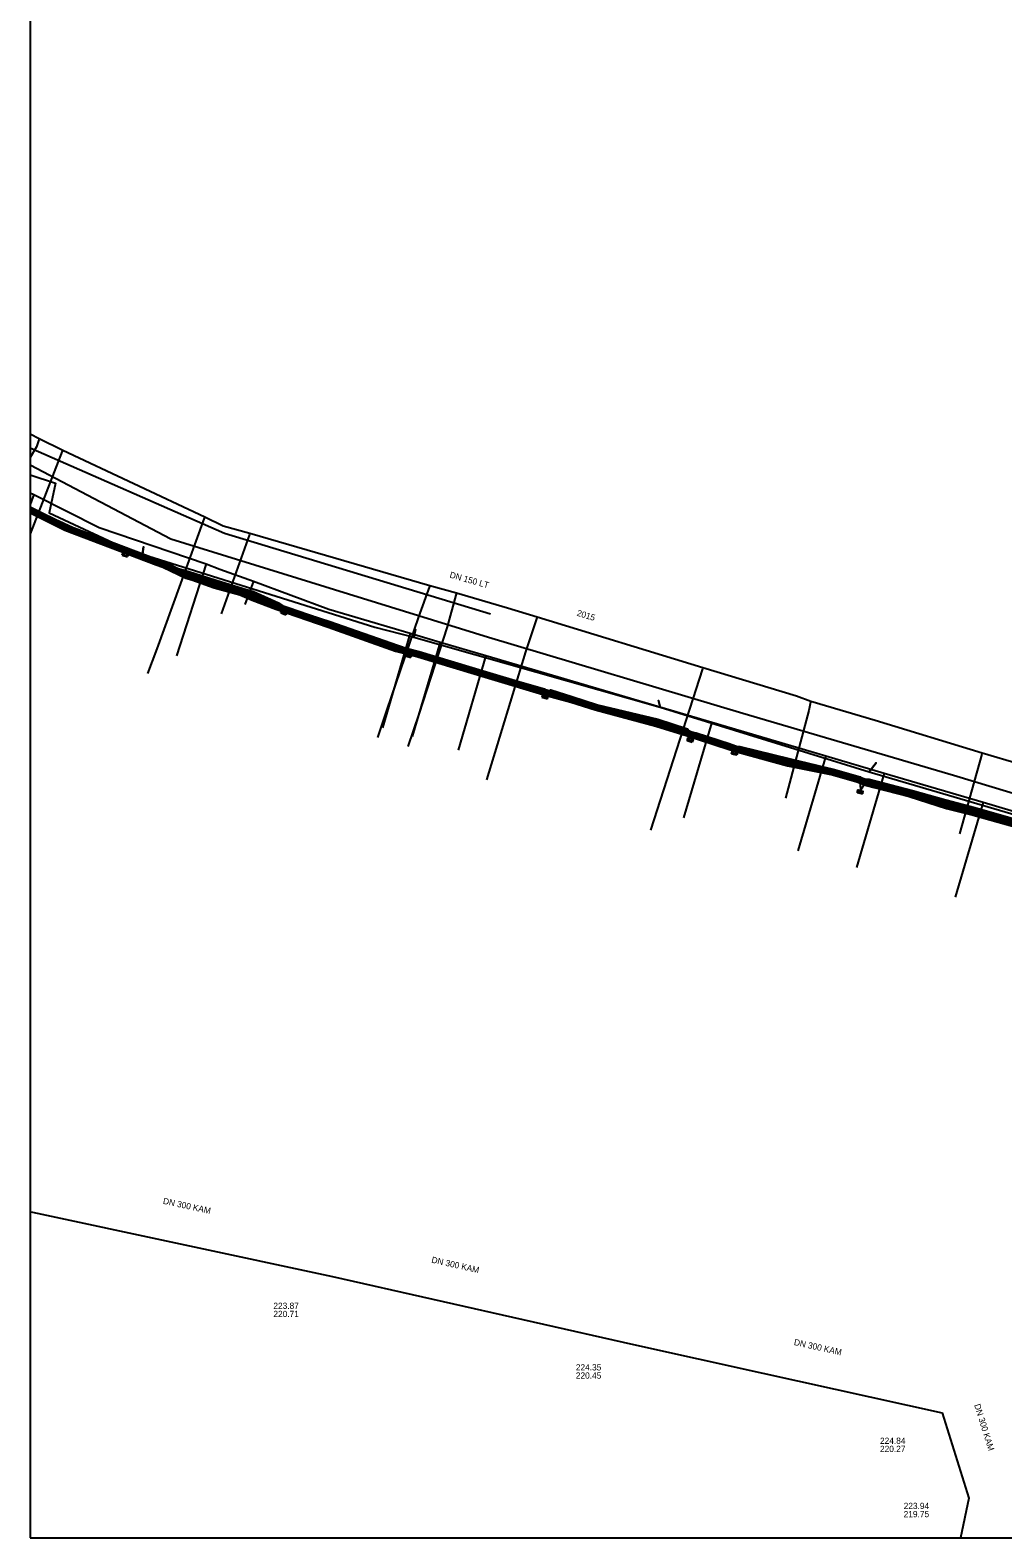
# Model space of a CAD drawing. Extents: x -599951 to -598963, y -1164095 to -1162939.
# Drawn here: x -599951.1 to -599826.1, y -1164094.7 to -1163901.1 of the extents above; entities that cross this region are included whole.
import ezdxf

# ---------------------------------------------------------------- set-up
doc = ezdxf.new("R2010")
doc.units = 0
for name, color, linetype in [('28', 7, 'Continuous'), ('31', 7, 'Continuous'), ('Level 1', 7, 'Continuous'), ('Vrstva 1', 7, 'Continuous'), ('Vrstva 13', 7, 'Continuous'), ('Vrstva 15', 7, 'Continuous'), ('Vrstva 16', 7, 'Continuous'), ('Vrstva 19', 7, 'Continuous'), ('Vrstva 42', 7, 'Continuous'), ('Vrstva 43', 7, 'Continuous'), ('Vrstva 44', 7, 'Continuous'), ('Vrstva 5', 7, 'Continuous'), ('Vrstva 53', 7, 'Continuous'), ('Vrstva 55', 7, 'Continuous'), ('Vrstva 58', 7, 'Continuous'), ('Vrstva 8', 7, 'Continuous')]:
    doc.layers.add(name, color=color, linetype=linetype)

# ---------------------------------------------------------------- blocks, each defined once
blk = doc.blocks.new('NN630')
at = {"layer": '31'}
for points in [[(-0.003, -0.7), (-0.703, 0)], [(-0.703, -0.7), (-0.703, 0), (0.697, 0), (0.697, -0.7)], [(-0.003, -0.7), (0.697, 0)], [(-0.703, -0.7), (0.697, -0.7)]]:
    blk.add_lwpolyline(points, dxfattribs=at)
blk = doc.blocks.new('NN620')
at = {"layer": '28'}
for points in [[(0.752, 0.004), (-0.748, 0.004)], [(-0.748, 0.004), (-0.748, -0.746)], [(0.752, -0.746), (0.752, 0.004)], [(-0.748, -0.746), (0.752, -0.746)], [(0.368, -0.18), (-0.376, -0.18)], [(-0.376, -0.18), (-0.376, -0.558)], [(-0.376, -0.558), (0.368, -0.558)], [(0.321, -0.227), (-0.329, -0.227)], [(-0.329, -0.227), (-0.329, -0.51)], [(-0.329, -0.51), (0.321, -0.51)], [(0.274, -0.274), (-0.281, -0.274)], [(-0.281, -0.274), (-0.281, -0.463)], [(-0.281, -0.463), (0.274, -0.463)], [(0.227, -0.321), (-0.234, -0.321)], [(-0.234, -0.321), (-0.234, -0.416)], [(-0.234, -0.416), (0.227, -0.416)], [(-0.193, -0.369), (0.185, -0.369)], [(0.227, -0.416), (0.227, -0.321)], [(0.274, -0.463), (0.274, -0.274)], [(0.321, -0.51), (0.321, -0.227)], [(0.368, -0.558), (0.368, -0.18)]]:
    blk.add_lwpolyline(points, dxfattribs=at)

msp = doc.modelspace()

# ---------------------------------------------------------------- linework, layer by layer
at = {"layer": 'Level 1'}
msp.add_line((-599926.14, -1163965.72), (-599951.125, -1163954.755), dxfattribs=at)
msp.add_lwpolyline([(-599891.96, -1163976.04), (-599926.14, -1163965.72)], dxfattribs=at)
at = {"layer": 'Vrstva 1'}
for p, q in [((-599926.14, -1163965.72), (-599951.125, -1163954.755)), ((-599891.96, -1163976.04), (-599926.14, -1163965.72))]:
    msp.add_line(p, q, dxfattribs=at)
at = {"layer": 'Vrstva 13'}
for points in [[(-599951.125, -1163952.918), (-599949.96, -1163953.52), (-599946.91, -1163954.98), (-599928.693, -1163963.548), (-599926.32, -1163964.71), (-599922.88, -1163965.66), (-599899.76, -1163972.37), (-599896.35, -1163973.33), (-599889.787, -1163975.267), (-599885.98, -1163976.39), (-599864.68, -1163982.92), (-599852.64, -1163986.57), (-599850.8, -1163987.22), (-599842.53, -1163989.68), (-599828.77, -1163993.88), (-599818.92, -1163996.8)], [(-599949.96, -1163953.52), (-599950.028, -1163953.686), (-599950.32, -1163954.59), (-599951.125, -1163955.956)], [(-599946.91, -1163954.98), (-599946.99, -1163955.13), (-599951.125, -1163965.737)], [(-599928.693, -1163963.548), (-599928.77, -1163963.73), (-599934.837, -1163980.507), (-599936.057, -1163983.688)], [(-599922.88, -1163965.66), (-599922.938, -1163965.82), (-599926.594, -1163976.031)], [(-599899.76, -1163972.37), (-599899.818, -1163972.529), (-599901.22, -1163976.42), (-599905.32, -1163988.42), (-599906.479, -1163991.902)], [(-599896.35, -1163973.33), (-599896.43, -1163973.61), (-599897.54, -1163977.7), (-599901.19, -1163988.92), (-599902.608, -1163993.068)], [(-599885.98, -1163976.39), (-599886.03, -1163976.536), (-599887.48, -1163980.89), (-599892.48, -1163997.355)], [(-599864.68, -1163982.92), (-599864.734, -1163983.09), (-599871.419, -1164003.786)], [(-599850.8, -1163987.22), (-599850.835, -1163987.348), (-599851.07, -1163988.42), (-599854.064, -1163999.693)], [(-599828.77, -1163993.88), (-599828.818, -1163994.062), (-599831.709, -1164004.271)]]:
    msp.add_lwpolyline(points, dxfattribs=at)
at = {"layer": 'Vrstva 16'}
msp.add_line((-599950.66, -1163960.7), (-599951.125, -1163961.971), dxfattribs=at)
for points in [[(-599951.125, -1163960.491), (-599950.66, -1163960.7), (-599942.27, -1163964.92), (-599928.49, -1163969.58), (-599926.77, -1163970.3), (-599922.43, -1163971.82), (-599912.76, -1163975.43), (-599902.28, -1163978.51), (-599898.44, -1163979.65), (-599892.56, -1163981.38), (-599863.53, -1163989.93), (-599848.86, -1163994.26), (-599841.36, -1163996.47), (-599828.66, -1164000.21), (-599821.46, -1164002.33)], [(-599928.49, -1163969.58), (-599932.31, -1163981.4)], [(-599922.43, -1163971.82), (-599923.52, -1163974.82)], [(-599902.28, -1163978.51), (-599905.86, -1163990.67)], [(-599898.44, -1163979.65), (-599902.02, -1163991.79)], [(-599892.56, -1163981.38), (-599896.14, -1163993.51)], [(-599863.53, -1163989.93), (-599867.15, -1164002.21)], [(-599848.86, -1163994.26), (-599852.46, -1164006.47)], [(-599841.36, -1163996.47), (-599844.94, -1164008.58)], [(-599828.66, -1164000.21), (-599832.25, -1164012.41)]]:
    msp.add_lwpolyline(points, dxfattribs=at)
at = {"layer": 'Vrstva 19'}
msp.add_lwpolyline([(-599951.125, -1163956.879), (-599933.03, -1163966.38), (-599892.24, -1163979.02), (-599859.53, -1163988.78), (-599832.49, -1163996.75), (-599788.49, -1164009.99), (-599755.73, -1164019.59), (-599723.17, -1164029.22), (-599687.59, -1164039.86)], dxfattribs=at)
at = {"layer": 'Vrstva 42'}
for points in [[(-599951.125, -1163962.512), (-599950.901, -1163962.608), (-599947.449, -1163964.059), (-599939.348, -1163967.839), (-599938.556, -1163968.123), (-599937.145, -1163968.466), (-599936.23, -1163968.928), (-599935.077, -1163969.363), (-599934.575, -1163969.483), (-599930.732, -1163970.584), (-599927.2, -1163971.675), (-599923.771, -1163972.754), (-599922.415, -1163973.146), (-599919.222, -1163974.622), (-599918.557, -1163975.035), (-599918.447, -1163975.186), (-599918.205, -1163975.283), (-599917.909, -1163975.295), (-599912.608, -1163976.995), (-599903.937, -1163980.035), (-599902.558, -1163980.505), (-599902.369, -1163980.655), (-599902.155, -1163980.707), (-599901.911, -1163980.664), (-599892.112, -1163983.624), (-599885.028, -1163985.649), (-599884.813, -1163986.454)], [(-599951.125, -1163962.729), (-599950.979, -1163962.792), (-599947.531, -1163964.241), (-599939.432, -1163968.021), (-599938.84, -1163968.24), (-599938.604, -1163968.317), (-599937.215, -1163968.654), (-599936.31, -1163969.112), (-599935.135, -1163969.554), (-599934.625, -1163969.677), (-599930.789, -1163970.776), (-599927.26, -1163971.865), (-599923.829, -1163972.946), (-599922.485, -1163973.334), (-599919.318, -1163974.798), (-599918.578, -1163975.261), (-599918.48, -1163975.69), (-599918.045, -1163975.449), (-599917.674, -1163975.58), (-599912.672, -1163977.185), (-599904.003, -1163980.225), (-599902.562, -1163980.716), (-599902.45, -1163981.19), (-599902.033, -1163980.838), (-599892.168, -1163983.816), (-599885.192, -1163985.811), (-599885.007, -1163986.506)], [(-599884.972, -1163986.402), (-599884.211, -1163985.799), (-599881.51, -1163986.625), (-599878.213, -1163987.714), (-599870.453, -1163989.544), (-599866.649, -1163990.805), (-599866.5, -1163990.984), (-599865.838, -1163991.294), (-599865.559, -1163991.315), (-599861.169, -1163992.735), (-599860.887, -1163992.907), (-599860.254, -1163993.063), (-599859.916, -1163993.043), (-599853.476, -1163994.623), (-599847.774, -1163996.013), (-599844.482, -1163996.964), (-599844.238, -1163997.122), (-599843.666, -1163997.253), (-599843.305, -1163997.233), (-599837.754, -1163998.693), (-599833.454, -1163999.904), (-599829.724, -1164000.884), (-599822.402, -1164002.984)], [(-599884.848, -1163986.558), (-599884.169, -1163986.021), (-599881.57, -1163986.815), (-599878.267, -1163987.906), (-599870.507, -1163989.736), (-599866.637, -1163991.019), (-599866.27, -1163992.05), (-599865.85, -1163991.68), (-599865.668, -1163991.491), (-599861.029, -1163992.991), (-599860.7, -1163993.3), (-599860.55, -1163993.74), (-599860.023, -1163993.221), (-599859.72, -1163993.297), (-599853.524, -1163994.817), (-599847.826, -1163996.207), (-599844.505, -1163997.167), (-599844.44, -1163998.72), (-599843.86, -1163997.82), (-599843.594, -1163997.574), (-599843.416, -1163997.41), (-599837.806, -1163998.886), (-599833.506, -1164000.096), (-599829.777, -1164001.076), (-599822.424, -1164003.186)]]:
    msp.add_lwpolyline(points, dxfattribs=at)
at = {"layer": 'Vrstva 44'}
for points in [[(-599951.125, -1163962.276), (-599946.38, -1163964.645), (-599934.695, -1163969.059), (-599933.793, -1163969.393), (-599930.872, -1163970.779), (-599930.127, -1163971.005), (-599927.251, -1163972.003), (-599923.95, -1163972.916), (-599922.348, -1163973.612), (-599919.319, -1163974.748), (-599912.601, -1163977.057), (-599903.972, -1163980.123), (-599901.119, -1163980.861), (-599892.044, -1163983.603), (-599884.617, -1163985.822)], [(-599951.125, -1163962.499), (-599946.46, -1163964.828), (-599934.765, -1163969.246), (-599933.871, -1163969.578), (-599930.951, -1163970.964), (-599930.189, -1163971.195), (-599927.31, -1163972.194), (-599924.017, -1163973.105), (-599922.423, -1163973.797), (-599919.386, -1163974.936), (-599912.667, -1163977.246), (-599904.031, -1163980.314), (-599901.173, -1163981.054), (-599892.101, -1163983.794), (-599884.672, -1163986.014)], [(-599930.98, -1163971.06), (-599933.91, -1163969.67), (-599934.8, -1163969.34), (-599946.5, -1163964.92), (-599951.125, -1163962.611)], [(-599951.125, -1163962.723), (-599946.54, -1163965.012), (-599934.835, -1163969.434), (-599933.949, -1163969.762), (-599931.023, -1163971.151), (-599930.251, -1163971.385), (-599927.37, -1163972.386), (-599924.083, -1163973.294), (-599922.497, -1163973.983), (-599919.454, -1163975.124), (-599912.733, -1163977.434), (-599904.089, -1163980.506), (-599901.227, -1163981.246), (-599892.159, -1163983.986), (-599884.728, -1163986.206)], [(-599951.125, -1163962.946), (-599946.62, -1163965.195), (-599934.905, -1163969.621), (-599934.027, -1163969.947), (-599931.088, -1163971.341), (-599930.313, -1163971.575), (-599927.429, -1163972.577), (-599924.15, -1163973.484), (-599922.572, -1163974.168), (-599919.521, -1163975.312), (-599912.799, -1163977.623), (-599904.148, -1163980.697), (-599901.281, -1163981.439), (-599892.216, -1163984.177), (-599884.783, -1163986.398)], [(-599930.98, -1163971.06), (-599930.22, -1163971.29), (-599927.34, -1163972.29), (-599924.05, -1163973.2), (-599922.46, -1163973.89), (-599919.42, -1163975.03), (-599912.7, -1163977.34), (-599904.06, -1163980.41), (-599901.2, -1163981.15), (-599892.13, -1163983.89), (-599884.7, -1163986.11), (-599881.55, -1163986.98), (-599878.42, -1163987.98), (-599870.62, -1163990.06), (-599866.56, -1163991.32), (-599861.32, -1163993), (-599860.07, -1163993.42), (-599853.73, -1163995.13), (-599847.94, -1163996.29), (-599844.77, -1163997.21), (-599843.52, -1163997.68), (-599842.56, -1163997.92), (-599838.04, -1163999.11), (-599833.27, -1164000.62), (-599829.82, -1164001.49), (-599822.36, -1164003.58)], [(-599884.783, -1163986.398), (-599881.636, -1163987.268), (-599878.504, -1163988.268), (-599870.703, -1163990.348), (-599866.65, -1163991.606), (-599861.414, -1163993.285), (-599860.157, -1163993.707), (-599853.799, -1163995.422), (-599848.011, -1163996.582), (-599844.865, -1163997.495), (-599843.609, -1163997.967), (-599842.635, -1163998.211), (-599838.123, -1163999.398), (-599833.352, -1164000.909), (-599829.897, -1164001.78), (-599822.434, -1164003.871)], [(-599884.728, -1163986.206), (-599881.579, -1163987.076), (-599878.448, -1163988.076), (-599870.648, -1163990.156), (-599866.59, -1163991.415), (-599861.351, -1163993.095), (-599860.099, -1163993.516), (-599853.753, -1163995.227), (-599847.964, -1163996.387), (-599844.802, -1163997.305), (-599843.55, -1163997.776), (-599842.585, -1163998.017), (-599838.068, -1163999.206), (-599833.297, -1164000.716), (-599829.846, -1164001.587), (-599822.385, -1164003.677)], [(-599884.672, -1163986.014), (-599881.521, -1163986.884), (-599878.392, -1163987.884), (-599870.592, -1163989.964), (-599866.53, -1163991.225), (-599861.289, -1163992.905), (-599860.041, -1163993.324), (-599853.707, -1163995.033), (-599847.916, -1163996.193), (-599844.738, -1163997.115), (-599843.49, -1163997.584), (-599842.535, -1163997.823), (-599838.012, -1163999.014), (-599833.243, -1164000.524), (-599829.794, -1164001.393), (-599822.335, -1164003.483)], [(-599884.617, -1163985.822), (-599881.464, -1163986.692), (-599878.336, -1163987.692), (-599870.537, -1163989.772), (-599866.47, -1163991.034), (-599861.226, -1163992.715), (-599859.983, -1163993.133), (-599853.661, -1163994.838), (-599847.869, -1163995.998), (-599844.675, -1163996.925), (-599843.431, -1163997.393), (-599842.485, -1163997.629), (-599837.957, -1163998.822), (-599833.188, -1164000.331), (-599829.743, -1164001.2), (-599822.286, -1164003.289)]]:
    msp.add_lwpolyline(points, dxfattribs=at)
at = {"layer": 'Vrstva 5'}
for p, q in [((-599951.125, -1164052.826), (-599950.82, -1164052.85)), ((-599950.82, -1164052.85), (-599912.29, -1164061.14)), ((-599912.29, -1164061.14), (-599873.59, -1164069.86)), ((-599833.92, -1164078.65), (-599830.51, -1164089.59)), ((-599830.51, -1164089.59), (-599831.58, -1164094.695))]:
    msp.add_line(p, q, dxfattribs=at)
msp.add_lwpolyline([(-599873.59, -1164069.86), (-599856.958, -1164073.545), (-599833.92, -1164078.65)], dxfattribs=at)
at = {"layer": 'Vrstva 53'}
msp.add_lwpolyline([(-599951.125, -1164094.695), (-598963.215, -1164094.695), (-598963.215, -1162939.4), (-599951.125, -1162939.4)], close=True, dxfattribs=at)
at = {"layer": 'Vrstva 55'}
msp.add_lwpolyline([(-599951.125, -1163958.165), (-599947.86, -1163959.25), (-599948.7, -1163963.03), (-599937.861, -1163968.08), (-599936.673, -1163968.349), (-599936.558, -1163967.429), (-599936.673, -1163968.349), (-599906.813, -1163977.74), (-599901.83, -1163979.005), (-599901.6, -1163978.046), (-599901.83, -1163979.005), (-599870.169, -1163988.012), (-599870.361, -1163987.131), (-599870.169, -1163988.012), (-599843.3, -1163996.292), (-599842.418, -1163995.142), (-599843.3, -1163996.292), (-599814.169, -1164004.878)], dxfattribs=at)
at = {"layer": 'Vrstva 58'}
for points in [[(-599822.31, -1164003.386), (-599829.769, -1164001.297), (-599833.215, -1164000.428), (-599837.984, -1163998.918), (-599842.51, -1163997.726), (-599843.46, -1163997.489), (-599844.707, -1163997.02), (-599847.892, -1163996.096), (-599853.684, -1163994.935), (-599860.012, -1163993.229), (-599861.258, -1163992.81), (-599866.5, -1163991.129), (-599870.565, -1163989.868), (-599878.364, -1163987.788), (-599881.493, -1163986.788), (-599884.645, -1163985.918), (-599892.072, -1163983.699), (-599901.146, -1163980.957), (-599904.001, -1163980.219), (-599912.634, -1163977.151), (-599919.352, -1163974.842), (-599922.385, -1163973.704), (-599923.983, -1163973.011), (-599927.28, -1163972.099), (-599930.158, -1163971.1), (-599930.908, -1163970.873), (-599933.832, -1163969.486), (-599934.73, -1163969.153), (-599946.42, -1163964.737), (-599951.125, -1163962.387)], [(-599951.125, -1163962.611), (-599946.5, -1163964.92), (-599934.8, -1163969.34), (-599933.91, -1163969.67), (-599930.98, -1163971.06), (-599930.22, -1163971.29), (-599927.34, -1163972.29), (-599924.05, -1163973.2), (-599922.46, -1163973.89), (-599919.42, -1163975.03), (-599912.7, -1163977.34), (-599904.06, -1163980.41), (-599901.2, -1163981.15), (-599892.13, -1163983.89), (-599884.7, -1163986.11), (-599881.55, -1163986.98), (-599878.42, -1163987.98), (-599870.62, -1163990.06), (-599866.56, -1163991.32), (-599861.32, -1163993), (-599860.07, -1163993.42), (-599853.73, -1163995.13), (-599847.94, -1163996.29), (-599844.77, -1163997.21), (-599843.52, -1163997.68), (-599842.56, -1163997.92), (-599838.04, -1163999.11), (-599833.27, -1164000.62), (-599829.82, -1164001.49), (-599822.36, -1164003.58)], [(-599951.125, -1163962.834), (-599946.58, -1163965.103), (-599934.87, -1163969.527), (-599933.988, -1163969.854), (-599931.052, -1163971.247), (-599930.282, -1163971.48), (-599927.4, -1163972.481), (-599924.117, -1163973.389), (-599922.535, -1163974.075), (-599919.488, -1163975.218), (-599912.766, -1163977.529), (-599904.119, -1163980.601), (-599901.254, -1163981.343), (-599892.188, -1163984.082), (-599884.755, -1163986.302), (-599881.607, -1163987.172), (-599878.476, -1163988.172), (-599870.675, -1163990.252), (-599866.62, -1163991.511), (-599861.382, -1163993.19), (-599860.128, -1163993.612), (-599853.776, -1163995.325), (-599847.988, -1163996.484), (-599844.833, -1163997.4), (-599843.58, -1163997.871), (-599842.61, -1163998.114), (-599838.096, -1163999.302), (-599833.325, -1164000.813), (-599829.871, -1164001.683), (-599822.41, -1164003.774)], [(-599951.125, -1163963.058), (-599946.66, -1163965.287), (-599934.94, -1163969.715), (-599934.066, -1163970.039), (-599931.125, -1163971.434), (-599930.344, -1163971.67), (-599927.459, -1163972.672), (-599924.184, -1163973.578), (-599922.61, -1163974.261), (-599919.555, -1163975.406), (-599912.832, -1163977.718), (-599904.177, -1163980.793), (-599901.308, -1163981.535), (-599892.245, -1163984.273), (-599884.811, -1163986.494), (-599881.664, -1163987.363), (-599878.532, -1163988.364), (-599870.731, -1163990.444), (-599866.68, -1163991.702), (-599861.445, -1163993.38), (-599860.186, -1163993.803), (-599853.821, -1163995.52), (-599848.035, -1163996.679), (-599844.896, -1163997.59), (-599843.639, -1163998.062), (-599842.659, -1163998.307), (-599838.151, -1163999.494), (-599833.379, -1164001.005), (-599829.923, -1164001.877), (-599822.459, -1164003.968)]]:
    msp.add_lwpolyline(points, dxfattribs=at)

# ---------------------------------------------------------------- block references
at = {"layer": 'Vrstva 43'}
for name, p, xscale, yscale, rotation in [('NN630', (-599938.84, -1163968.24), 0.49999999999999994, 0.5000000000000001, -18.000000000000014), ('NN630', (-599918.48, -1163975.69), 0.5000000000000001, 0.5, -18.999999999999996), ('NN630', (-599902.45, -1163981.19), 0.5000000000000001, 0.5, -17.000000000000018), ('NN620', (-599884.907, -1163986.486), 0.5, 0.5000000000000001, -16.000000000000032), ('NN630', (-599866.27, -1163992.05), 0.5, 0.5000000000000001, -16.000000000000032), ('NN630', (-599860.58, -1163993.73), 0.5, 0.5, -13.000000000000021), ('NN630', (-599844.44, -1163998.72), 0.5, 0.5, -13.000000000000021)]:
    msp.add_blockref(name, p, dxfattribs=dict(at, xscale=xscale, yscale=yscale, rotation=rotation))

# ---------------------------------------------------------------- texts
at = {"layer": 'Vrstva 15'}
for s, rotation, p in [('DN 150 LT', 344.27677, (-599897.279, -1163971.352)), ('2015', 342.95589, (-599880.941, -1163976.24))]:
    msp.add_text(s, height=0.8, rotation=rotation, dxfattribs=at).set_placement(p)
at = {"layer": 'Vrstva 8'}
for rotation, p in [(347.85752, (-599934.107, -1164051.782)), (347.302, (-599899.609, -1164059.337)), (347.50637, (-599853.03, -1164069.915)), (287.31227, (-599829.821, -1164077.631))]:
    msp.add_text('DN 300 KAM', height=0.8, rotation=rotation, dxfattribs=at).set_placement(p)
for s, p in [('223.87', (-599919.866, -1164065.288)), ('220.71', (-599919.866, -1164066.338)), ('224.35', (-599881.002, -1164073.196)), ('220.45', (-599881.002, -1164074.246)), ('224.84', (-599841.914, -1164082.621)), ('220.27', (-599841.914, -1164083.671)), ('223.94', (-599838.871, -1164090.993)), ('219.75', (-599838.871, -1164092.043))]:
    msp.add_text(s, height=0.8, dxfattribs=at).set_placement(p)

doc.saveas('drawing.dxf')
